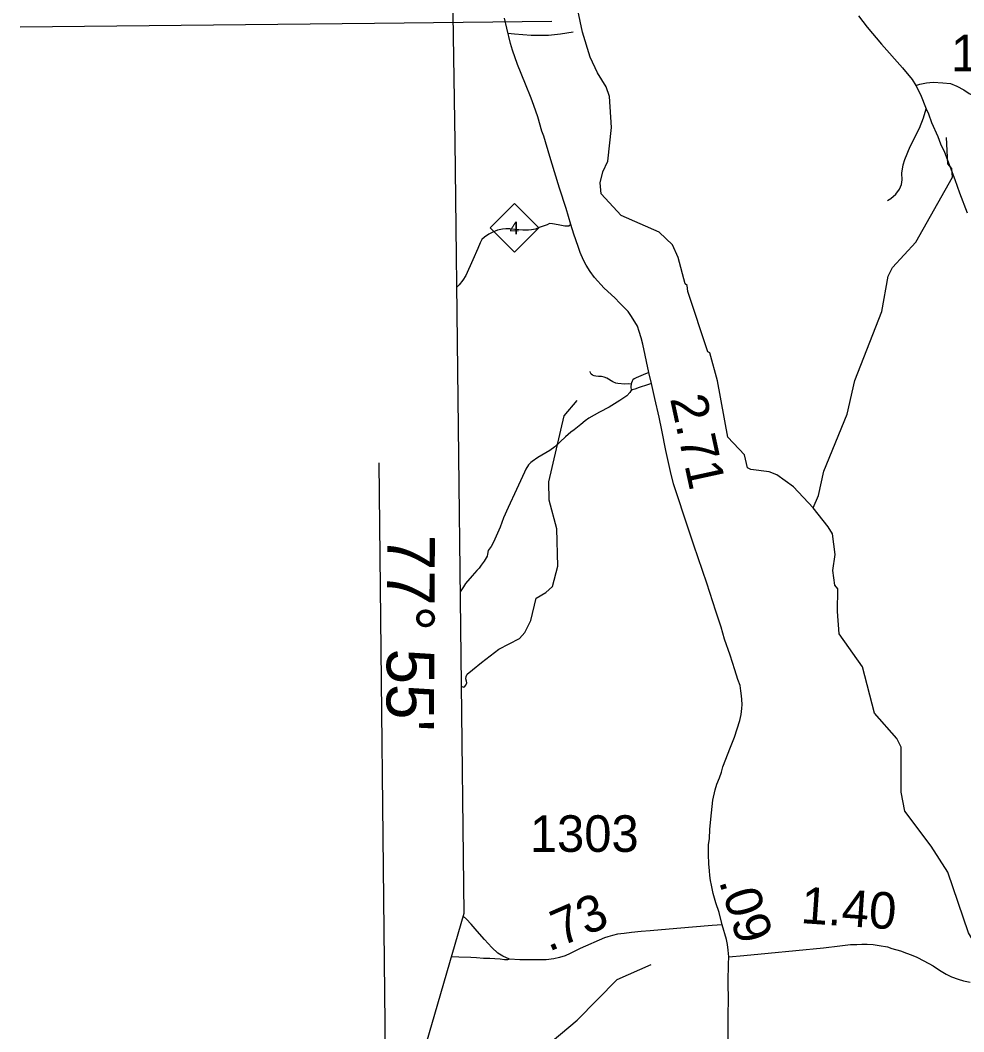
# Model space of a CAD drawing. Extents: x 2290615 to 2522933, y 819489 to 1012715.
# Drawn here: x 2314246 to 2327135, y 958270 to 972091 of the extents above; entities that cross this region are included whole.
import ezdxf

# ---------------------------------------------------------------- set-up
doc = ezdxf.new("R2010")
doc.units = 0
for name, color, linetype in [('Exist Boundary Political CountyLine', 7, 'Continuous'), ('Exist Hydrographic Creek Single Shore', 7, 'Continuous'), ('Exist Hydrographic Misc Water Feature', 7, 'Continuous'), ('Exist Road Non-System Type 51', 7, 'Continuous'), ('Exist Road Primary NC Attributed', 7, 'Continuous'), ('Exist Road Primary NC Mileage Hundredths English Label', 7, 'Continuous'), ('Exist Road Primary NC Shield CELL', 7, 'Continuous'), ('Exist Road Primary NC Shield Number Label', 7, 'Continuous'), ('Exist Road Secondary Mileage Hundredths English Label', 7, 'Continuous'), ('Exist Road Secondary Type 51 Attributed', 7, 'Continuous'), ('Exist Road Secondary Type 51 Number Label', 7, 'Continuous'), ('Map Preparation Longitude Latitude Label', 7, 'Continuous'), ('Map Preparation Longitude Latitude Lines', 7, 'Continuous')]:
    doc.layers.add(name, color=color, linetype=linetype)

msp = doc.modelspace()

# ---------------------------------------------------------------- linework, layer by layer
at = {"layer": 'Exist Boundary Political CountyLine'}
msp.add_lwpolyline([(2320108, 975053), (2320181, 970432), (2320307, 959884), (2316687, 947423)], dxfattribs=at)
at = {"layer": 'Exist Hydrographic Creek Single Shore'}
for points in [[(2325079, 965429), (2324810, 965716), (2324583, 965881), (2324475, 965922), (2324225, 965952), (2324183, 965976), (2324138, 966151), (2323911, 966392), (2323770, 967164), (2323665, 967547), (2323640, 967562), (2323365, 968385), (2323356, 968466), (2323330, 968491), (2323235, 968849), (2323158, 969023), (2322973, 969196), (2322454, 969424), (2322184, 969721), (2322166, 969871), (2322206, 970021), (2322271, 970165), (2322324, 970623), (2322295, 971049), (2322252, 971181), (2322133, 971370), (2322031, 971586), (2321927, 971926), (2321865, 972226)], [(2320270, 962992), (2320300, 962979), (2320313, 962983), (2320334, 963006), (2320347, 963036), (2320342, 963060), (2320334, 963091), (2320336, 963125), (2320353, 963155), (2320423, 963213), (2320546, 963315), (2320785, 963499), (2321067, 963645), (2321141, 963727), (2321222, 963888), (2321295, 964196), (2321426, 964274), (2321517, 964356), (2321589, 964632), (2321575, 965140), (2321472, 965533), (2321468, 965782), (2321675, 966684), (2321856, 966895)], [(2327681, 958242), (2327595, 958601), (2327603, 958881), (2327600, 958930), (2327571, 959011), (2327200, 959621), (2326916, 960449), (2326688, 960804), (2326332, 961285), (2326280, 961542), (2326281, 962160), (2326222, 962275), (2325918, 962621), (2325753, 963254), (2325431, 963707), (2325412, 964014), (2325417, 964323), (2325374, 964374), (2325348, 964573), (2325378, 964791), (2325341, 965072), (2325282, 965171), (2325079, 965429)]]:
    msp.add_lwpolyline(points, dxfattribs=at)
at = {"layer": 'Exist Hydrographic Misc Water Feature'}
for points in [[(2325079, 965429), (2325152, 965596), (2325225, 965930), (2325541, 966708), (2325645, 967169), (2326018, 968113), (2326103, 968596), (2326160, 968713), (2326482, 969058), (2326980, 969948), (2326971, 970063), (2326920, 970129), (2326899, 970490)], [(2320436, 957215), (2320448, 957234), (2320526, 957350), (2320634, 957433), (2320798, 957660), (2321038, 957837), (2321369, 958025), (2321856, 958429), (2322400, 958986), (2322864, 959189)]]:
    msp.add_lwpolyline(points, dxfattribs=at)
at = {"layer": 'Exist Road Non-System Type 51'}
for points in [[(2320909, 971915), (2320999, 971906), (2321226, 971888), (2321461, 971885), (2321625, 971906), (2321800, 971933)], [(2326482, 971201), (2326533, 971218), (2326626, 971237), (2326716, 971244), (2326848, 971237), (2326952, 971224), (2327039, 971189), (2327137, 971138), (2327208, 971091), (2327256, 971065), (2327368, 971041), (2327530, 971022), (2327740, 971015), (2327963, 971001), (2328054, 971000)], [(2326094, 969629), (2326139, 969656), (2326209, 969712), (2326258, 969781), (2326283, 969845), (2326293, 969909), (2326288, 970003), (2326306, 970114), (2326330, 970188), (2326404, 970364), (2326529, 970614), (2326587, 970758), (2326623, 970882)], [(2326094, 969629), (2326139, 969656), (2326209, 969712), (2326258, 969781), (2326283, 969845), (2326293, 969909), (2326288, 970003), (2326306, 970114), (2326330, 970188), (2326404, 970364), (2326529, 970614), (2326587, 970758), (2326623, 970882)], [(2321769, 969299), (2321738, 969279), (2321686, 969279), (2321593, 969295), (2321515, 969307), (2321477, 969313), (2321443, 969296), (2321335, 969257), (2321285, 969236), (2321229, 969226), (2321187, 969223), (2321110, 969222), (2321003, 969232), (2320934, 969241), (2320881, 969242), (2320833, 969236), (2320764, 969222), (2320700, 969194), (2320648, 969167), (2320588, 969126), (2320553, 969095), (2320528, 969050), (2320497, 968973), (2320429, 968816), (2320332, 968603), (2320294, 968541), (2320242, 968475), (2320205, 968439)], [(2322593, 967118), (2322553, 967121), (2322507, 967120), (2322408, 967126), (2322384, 967132), (2322342, 967151), (2322258, 967198), (2322223, 967215), (2322185, 967222), (2322145, 967224), (2322109, 967227), (2322084, 967230), (2322065, 967240), (2322047, 967257), (2322038, 967275), (2322033, 967291)], [(2322834, 967277), (2322755, 967247), (2322658, 967205), (2322634, 967193), (2322615, 967176), (2322605, 967157), (2322598, 967137), (2322593, 967118)], [(2322595, 967033), (2322587, 967027), (2322574, 967005), (2322533, 966960), (2322437, 966897), (2322292, 966806), (2322161, 966735), (2322085, 966694), (2322012, 966654), (2321965, 966617), (2321904, 966565), (2321812, 966494), (2321768, 966463), (2321696, 966399), (2321623, 966331), (2321548, 966261), (2321479, 966214), (2321315, 966116), (2321238, 966061)], [(2322593, 967118), (2322588, 967087), (2322588, 967068), (2322595, 967033)], [(2322870, 967126), (2322816, 967110), (2322703, 967073), (2322643, 967052), (2322606, 967042), (2322595, 967033)], [(2321238, 966061), (2321221, 966049), (2321190, 966016), (2321152, 965955), (2321135, 965916), (2321026, 965681), (2320912, 965431), (2320847, 965290), (2320800, 965164), (2320709, 964958), (2320677, 964900), (2320639, 964844), (2320630, 964797), (2320624, 964770), (2320585, 964699), (2320543, 964643), (2320515, 964603), (2320484, 964571), (2320420, 964500), (2320329, 964396), (2320300, 964351), (2320255, 964283)], [(2320930, 959262), (2320900, 959254), (2320861, 959252), (2320804, 959261), (2320731, 959267), (2320660, 959273), (2320574, 959273), (2320478, 959280), (2320402, 959286), (2320236, 959288), (2320135, 959292)]]:
    msp.add_lwpolyline(points, dxfattribs=at)
at = {"layer": 'Exist Road Primary NC Attributed'}
for points in [[(2323833, 959733), (2323792, 959899), (2323748, 960032), (2323712, 960159), (2323691, 960272), (2323675, 960335), (2323666, 960407), (2323660, 960471), (2323654, 960565), (2323649, 960690), (2323649, 960755), (2323650, 960825), (2323660, 960913), (2323668, 961034), (2323679, 961175), (2323707, 961433), (2323741, 961575), (2323761, 961655), (2323797, 961738), (2323826, 961817), (2323845, 961889), (2323949, 962158), (2324005, 962294), (2324077, 962521), (2324093, 962604), (2324103, 962688), (2324106, 962742), (2324103, 962810), (2324099, 962861), (2324089, 962930), (2324080, 962999), (2324050, 963081), (2324009, 963216), (2323945, 963415), (2323869, 963636), (2323820, 963798), (2323747, 964017), (2323624, 964399), (2323448, 964919), (2323379, 965125), (2323169, 965756), (2323128, 965927), (2323067, 966210), (2323011, 966490), (2322973, 966669), (2322917, 966922), (2322870, 967126), (2322834, 967277), (2322749, 967665), (2322728, 967750), (2322703, 967838), (2322678, 967910), (2322598, 968045), (2322549, 968110), (2322439, 968227), (2322367, 968298), (2322221, 968430), (2322092, 968574), (2322030, 968658), (2321975, 968746), (2321941, 968812), (2321897, 968917), (2321868, 969000), (2321810, 969167), (2321769, 969299), (2321703, 969519), (2321612, 969796), (2321545, 970020), (2321479, 970229), (2321399, 970506), (2321369, 970574), (2321317, 970771), (2321264, 970926), (2321226, 971025), (2321149, 971219), (2321041, 971484), (2320970, 971680), (2320945, 971771), (2320893, 971980), (2320863, 972117)], [(2323925, 959293), (2323915, 959386), (2323906, 959462), (2323895, 959532), (2323833, 959733)], [(2323894, 955087), (2323896, 955350), (2323898, 955553), (2323904, 956530), (2323908, 957102), (2323909, 957311), (2323909, 957564), (2323917, 957763), (2323915, 958042), (2323918, 958391), (2323918, 958523), (2323920, 958688), (2323918, 958959), (2323921, 959195), (2323925, 959293)]]:
    msp.add_lwpolyline(points, dxfattribs=at)
at = {"layer": 'Exist Road Primary NC Shield CELL'}
msp.add_lwpolyline([(2320664, 969255), (2320997, 969588), (2321330, 969255), (2320997, 968922)], close=True, dxfattribs=at)
at = {"layer": 'Exist Road Secondary Type 51 Attributed'}
for points in [[(2325697, 972150), (2325816, 971998), (2326013, 971765), (2326298, 971440), (2326430, 971283), (2326482, 971201), (2326545, 971076), (2326623, 970882), (2326653, 970810), (2326696, 970694), (2326783, 970502), (2326819, 970403), (2326870, 970286), (2327012, 969916), (2327076, 969732), (2327184, 969461)], [(2323833, 959733), (2323699, 959720), (2323216, 959679), (2322850, 959651), (2322727, 959641), (2322595, 959627), (2322496, 959615), (2322406, 959602), (2322338, 959587), (2322271, 959567), (2322227, 959552), (2321895, 959408), (2321760, 959341), (2321691, 959306), (2321613, 959285), (2321537, 959268), (2321430, 959253), (2321262, 959251), (2321070, 959251), (2320930, 959262), (2320839, 959302), (2320772, 959346), (2320690, 959421), (2320590, 959533), (2320489, 959643), (2320405, 959742), (2320341, 959808), (2320298, 959850)], [(2323925, 959293), (2324131, 959313), (2324465, 959345), (2325218, 959417), (2325444, 959445), (2325515, 959454), (2325587, 959461), (2325675, 959464), (2325744, 959467), (2325815, 959467), (2325900, 959461), (2325979, 959451), (2326094, 959429), (2326154, 959409), (2326273, 959376), (2326352, 959346), (2326415, 959321), (2326494, 959288), (2326592, 959241), (2326717, 959171), (2326805, 959112), (2326894, 959058), (2326970, 959021), (2327061, 958987), (2327133, 958967), (2327223, 958949)]]:
    msp.add_lwpolyline(points, dxfattribs=at)
at = {"layer": 'Map Preparation Longitude Latitude Lines'}
msp.add_line((2319305, 951702), (2319148, 966042), dxfattribs=at)
msp.add_lwpolyline([(2314246, 972001), (2319083, 972052), (2321509, 972080)], dxfattribs=at)

# ---------------------------------------------------------------- texts
at = {"layer": 'Exist Road Primary NC Mileage Hundredths English Label'}
for s, rotation, p in [('2.71', 282.2822, (2323121, 966923)), ('.09', 287.0329, (2323788, 960328))]:
    msp.add_text(s, height=500, rotation=rotation, dxfattribs=at).set_placement(p)
at = {"layer": 'Exist Road Primary NC Shield Number Label'}
msp.add_text('4', height=175, dxfattribs=at).set_placement((2320930, 969165))
at = {"layer": 'Exist Road Secondary Mileage Hundredths English Label'}
for s, rotation, p in [('.73', 23.4574, (2321466, 959359)), ('1.40', 356.0525, (2324899, 959756))]:
    msp.add_text(s, height=500, rotation=rotation, dxfattribs=at).set_placement(p)
at = {"layer": 'Exist Road Secondary Type 51 Number Label'}
for s, p in [('1300', (2326962, 971392)), ('1303', (2321207, 960728))]:
    msp.add_text(s, height=500, rotation=360, dxfattribs=at).set_placement(p)
at = {"layer": 'Map Preparation Longitude Latitude Label'}
msp.add_text("77° 55'", height=650, rotation=269.7075, dxfattribs=at).set_placement((2319261, 965062))

doc.saveas('drawing.dxf')
